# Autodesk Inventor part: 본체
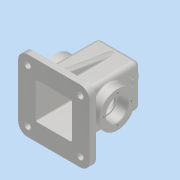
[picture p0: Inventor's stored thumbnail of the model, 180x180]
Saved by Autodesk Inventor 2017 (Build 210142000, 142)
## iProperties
Part Number: 본체
Material: 알루미늄 6061
Document SubType Name: Modeling
Designer: MRC
Density: 2.7 g/cm^3
Appearance: 알루미늄 - 평지
Mass: 753.626 g
Surface Area: 864.209 cm^2
Volume: 279.121 cm^3
Author: MRC
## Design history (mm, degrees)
sketch "스케치1"
  geometry: L1 (-34, 34)-(34, 34); L2 (34, 34)-(34, -34); L3 (34, -34)-(-34, -34); L4 (-34, -34)-(-34, 34); L5 (-34, 34)-(34, -34); L6 (34, 34)-(-34, -34); 1 further point
  constraints: 12 end point, 2 midpoint, 2 parallel, 1 horizontal, 1 perpendicular
  dimensions: "d0" = 68 distance of L2.end L3.end; "d1" = 68 distance of L1.end L2.end
extrude "돌출1" new body sketch "스케치1" distance "d2" = 53; taper "d4" = 0 deg; dims "d3" = 52, "d5" = 0
fillet "모깎기1" dims "d6" = 8
fillet "모깎기2" dims "d7" = 8
feature "쉘1" dims "d8" = 5
node "작업 평면1"
sketch "스케치3"
  geometry: C1 r 28.5 at (0, 0); 1 further point
  constraints: 1 centre point, 1 coincident
  dimensions: "d11" = 57 diameter of C1
extrude "돌출2" join sketch "스케치3" stored distance "d12" = 53; taper "d13" = 0 deg
fillet "모깎기3" dims "d14" = 3
hole "구멍1" diameter "d17" = 30; stored, may be unused: countersink angle "d21" = 90 deg, drill point angle "d23" = 118 deg; dims "d15" = 10, "d16" = 10, "d18" = 6, "d19" = 35, "d20" = 17, "d22" = 8
sketch "스케치4"
  geometry: C1 r 17.5 at (0, 0) reference; 1 further point
  constraints: 1 vertical alignment
  dimensions: "d24" = 22 distance of C1.centre point (0, 22)
hole "구멍2" sketch "스케치4" at (0, 22) diameter "d25" = 3.242; stored, may be unused: countersink angle "d29" = 90 deg, drill point angle "d31" = 118 deg; dims "d26" = 8, "d27" = 35, "d28" = 17, "d30" = 10
chamfer "모따기1" distance "d35" = 1; stored, may be unused: second distance "d36" = 2, angle "d37" = 45 deg
fillet "모깎기4" dims "d38" = 0.3
fillet "모깎기5" dims "d39" = 3
sketch "스케치5"
  geometry: C1 r 20 at (0, 0); 1 further point
  constraints: 1 centre point, 1 coincident
  dimensions: "d40" = 40 diameter of C1
extrude "돌출3" join sketch "스케치5" distance "d41" = 10; taper "d42" = 0 deg
feature "면 기울기1" dims angle "d43" = 8 deg
hole "구멍3" diameter "d46" = 22.835; stored, may be unused: countersink angle "d50" = 90 deg, drill point angle "d52" = 118 deg; dims "d44" = 10, "d45" = 10, "d47" = 50, "d48" = 35, "d49" = 17, "d51" = 59.3
sketch "스케치6"
  geometry: L1 (-26, -34)-(26, -34) reference; L2 (34, -26)-(34, 26) reference; L3 (26, 34)-(-26, 34) reference; L4 (-34, 26)-(-34, -26) reference; L5 (-57, 57)-(57, 57); L6 (57, 57)-(57, -57); L7 (57, -57)-(-57, -57); L8 (-57, -57)-(-57, 57); L9 (-57, 57)-(57, -57); L10 (57, 57)-(-57, -57); A1 r 8 centre (-26, -26) between (-34, -26) and (-26, -34) reference; A2 r 8 centre (26, -26) between (26, -34) and (34, -26) reference; A3 r 8 centre (26, 26) between (34, 26) and (26, 34) reference; A4 r 8 centre (-26, 26) between (-26, 34) and (-34, 26) reference; 1 further point
  constraints: 12 end point, 2 midpoint, 2 parallel, 1 horizontal, 1 perpendicular
  dimensions: "d53" = 114 distance of L6.end L7.end; "d54" = 114 distance of L5.end L6.end
extrude "돌출4" join sketch "스케치6" distance "d55" = 10; taper "d56" = 0 deg
fillet "모깎기6" dims "d57" = 15
sketch "스케치7"
  geometry: A1 r 15 centre (-42, -42) between (-57, -42) and (-42, -57) reference; A2 r 15 centre (42, -42) between (42, -57) and (57, -42) reference; A3 r 15 centre (42, 42) between (57, 42) and (42, 57) reference; A4 r 15 centre (-42, 42) between (-42, 57) and (-57, 42) reference; 5 further points
  constraints: 4 coincident
hole "구멍4" sketch "스케치7" at (42, -42), (-42, -42), (-42, 42), (42, 42) diameter "d58" = 10; stored, may be unused: countersink angle "d62" = 90 deg, drill point angle "d64" = 118 deg; dims "d59" = 50, "d60" = 18, "d61" = 2, "d63" = 59.3
sketch "스케치8"
  geometry: L1 (-42, 49)-(-27.378, 46.422); L2 (-42, 51)-(-42, 33) reference; L3 (-42, 57)-(-52, 57) reference; 1 further point
  constraints: 2 end point, 1 point on line
  dimensions: "d65" = 8 distance from line of L1.start L3; "d66" = 10 deg angle of L1 L3
feature "리브1" sketch "스케치8" dims "d67" = 1, "d68" = 10, "d69" = 0, "d70" = 0, "d71" = 1, "d72" = 1
fillet "모깎기7" dims "d73" = 3
fillet "모깎기8" dims "d74" = 3
fillet "모깎기9" dims "d75" = 3
fillet "모깎기10" dims "d76" = 3
fillet "모깎기11" dims "d77" = 3
sketch "스케치9"
  geometry: L1 (-8, 0)-(-8, -84) reference; L2 (46, 18)-(6, 18) reference; 1 further point
  constraints: 1 other
  dimensions: "d78" = 34 distance from line of point (26, -7) L1; "d79" = 25 distance from line of point (26, -7) L2
feature "엠보싱1" sketch "스케치9" dims "d0" = 68, "d1" = 68, "d80" = 0.5, "d81" = 0
node "솔리드1"
pattern_circular "원형 패턴1" dims angle "d33" = 360 deg
mirror "미러1"
mirror "미러2"
other parameters: "d10" = 49
